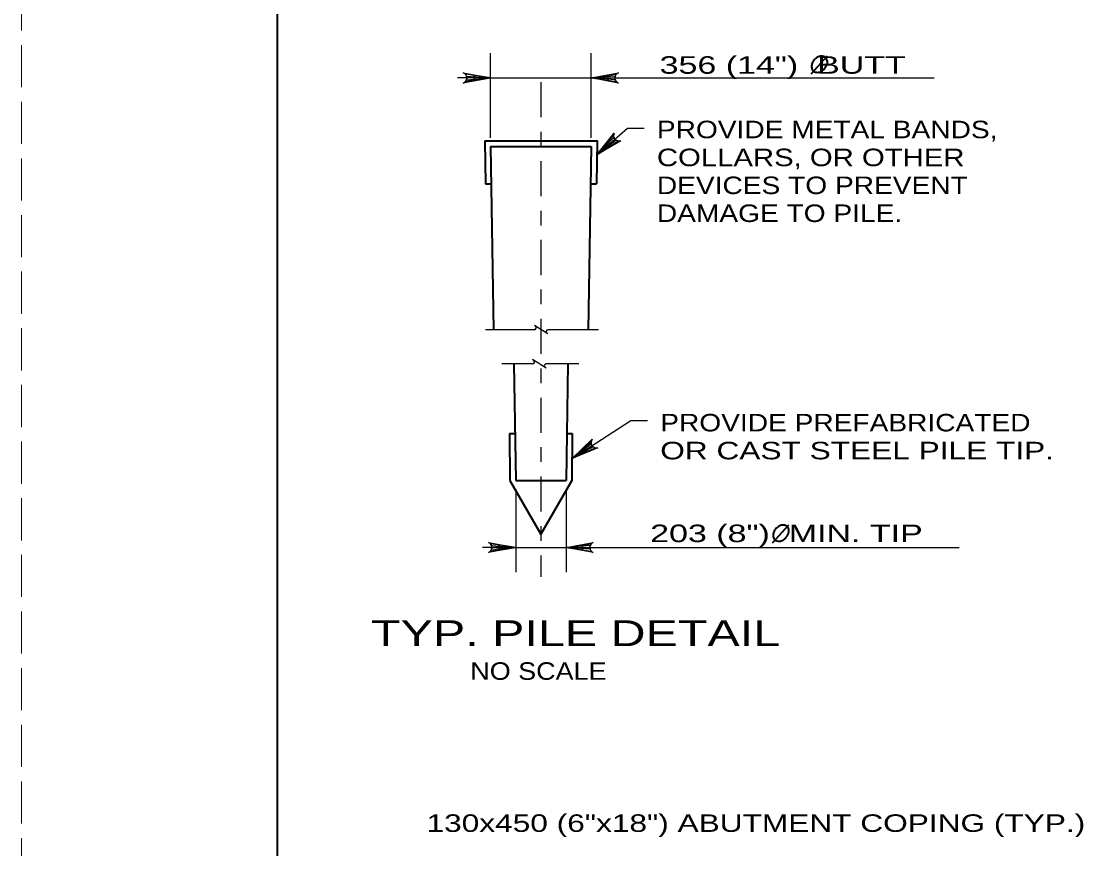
# Model space of a CAD drawing. Extents: x -6.4 to 73.1, y -66 to 0.
# Drawn here: x 0 to 7.37, y -14.43 to -8.76 of the extents above; entities that cross this region are included whole.
import ezdxf
from ezdxf.enums import TextEntityAlignment as Align

# ---------------------------------------------------------------- set-up
doc = ezdxf.new("R2010")
doc.units = 0
doc.header["$LTSCALE"] = 0.048
doc.linetypes.add('DOT_DASHED', pattern=[7.7, 5, -1.2, 0.3, -1.2])
doc.linetypes.add('LONG_DASHED', pattern=[7.5, 6, -1.5])
for name, color, linetype, lineweight in [('1', 7, 'Continuous', 13), ('4', 7, 'Continuous', 25), ('5', 7, 'Continuous', 25), ('63', 7, 'LONG_DASHED', 13)]:
    doc.layers.add(name, color=color, linetype=linetype, lineweight=lineweight)

msp = doc.modelspace()

# ---------------------------------------------------------------- hatches: boundary and pattern name
at = {"layer": '5'}
for points in [[(3.09875, -9.1305), (3.09875, -9.16825), (3.21217, -9.14933)], [(4.01483, -9.1305), (4.01483, -9.16825), (3.90142, -9.14933)], [(4.03808, -9.615), (4.01333, -9.58642), (3.94, -9.67492)], [(3.8765, -11.70867), (3.856, -11.67692), (3.77092, -11.75425)], [(3.27108, -12.34575), (3.27108, -12.3835), (3.38442, -12.36467)], [(3.8425, -12.34575), (3.8425, -12.3835), (3.72908, -12.36467)]]:
    msp.add_hatch(color=256, dxfattribs=at).paths.add_polyline_path(points)

# ---------------------------------------------------------------- linework, layer by layer
at = {"layer": '1', "lineweight": 35}
msp.add_lwpolyline([(1.75, -21.25), (33.25, -21.25), (33.25, -0.75), (1.75, -0.75)], close=True, dxfattribs=at)
at = {"layer": '4', "linetype": 'DOT_DASHED'}
msp.add_line((3.55675, -9.179), (3.55675, -12.56558), dxfattribs=at)
at = {"layer": '4', "lineweight": 35}
for p, q in [((3.17208, -9.5795), (3.17675, -9.87533)), ((3.21217, -9.61892), (3.23192, -10.87383)), ((3.21217, -9.61892), (3.90142, -9.61892)), ((3.90142, -9.61892), (3.88167, -10.87383)), ((3.17675, -9.87533), (3.21617, -9.87533)), ((3.89742, -9.87533), (3.93683, -9.87533)), ((3.37183, -11.10742), (3.38442, -11.90617)), ((3.74175, -11.10742), (3.72908, -11.90617)), ((3.34117, -11.58458), (3.34508, -11.90675)), ((3.34117, -11.58458), (3.38058, -11.58458)), ((3.733, -11.58458), (3.77233, -11.58458)), ((3.77233, -11.58458), (3.7685, -11.90675)), ((3.34508, -11.90675), (3.55675, -12.2735)), ((3.38442, -11.90617), (3.72908, -11.90617)), ((3.7685, -11.90675), (3.55675, -12.2735))]:
    msp.add_line(p, q, dxfattribs=at)
at = {"layer": '4'}
for p, q in [((3.51283, -10.87383), (3.17783, -10.87383)), ((3.60508, -10.90283), (3.51267, -10.84475)), ((3.95233, -10.87383), (3.60608, -10.87383)), ((3.50042, -11.10742), (3.28892, -11.10742)), ((3.59258, -11.1365), (3.50025, -11.07842)), ((3.81633, -11.10742), (3.59367, -11.10742))]:
    msp.add_line(p, q, dxfattribs=at)
at = {"layer": '4', "lineweight": 35}
msp.add_lwpolyline([(3.17208, -9.5795), (3.9415, -9.5795), (3.93683, -9.87533)], dxfattribs=at)
at = {"layer": '4'}
for centre, start, end in [((3.51161, -10.8602), 275.32859, 57.86724), ((3.60612, -10.88742), 90, 240), ((3.49915, -11.09384), 275.32859, 57.86724), ((3.59366, -11.12105), 90, 240)]:
    msp.add_arc(centre, 0.01364, start, end, dxfattribs=at)
at = {"layer": '5'}
for p, q in [((3.21217, -9.55983), (3.21217, -8.97925)), ((3.90142, -9.55983), (3.90142, -8.97925)), ((3.21217, -9.14933), (2.98533, -9.14933)), ((3.21217, -9.14933), (6.251, -9.14933)), ((3.90142, -9.14933), (4.12825, -9.14933)), ((3.38442, -11.96517), (3.38442, -12.53475)), ((3.72908, -11.96517), (3.72908, -12.53475)), ((3.38442, -12.36467), (3.15767, -12.36467)), ((3.38442, -12.36467), (6.42117, -12.36467)), ((3.8425, -12.36467), (3.95592, -12.36467))]:
    msp.add_line(p, q, dxfattribs=at)
at = {"layer": '5', "lineweight": 35}
for p, q in [((5.407, -9.12167), (5.519, -8.999)), ((5.14342, -12.33242), (5.25542, -12.20983))]:
    msp.add_line(p, q, dxfattribs=at)
at = {"layer": '5'}
for points in [[(3.21217, -9.14933), (3.02575, -9.18425), (3.04008, -9.17433), (3.0475, -9.16183), (3.04967, -9.14933), (3.0475, -9.13683), (3.04008, -9.12433), (3.02575, -9.11442), (3.21217, -9.14933), (3.04008, -9.12433), (3.0475, -9.13683), (3.21217, -9.14933), (3.04967, -9.14933), (3.0475, -9.16183), (3.21217, -9.14933), (3.04008, -9.17433)], [(3.90142, -9.14933), (4.08783, -9.11442), (4.0735, -9.12433), (4.06608, -9.13683), (4.06392, -9.14933), (4.06608, -9.16183), (4.0735, -9.17433), (4.08783, -9.18425), (3.90142, -9.14933), (4.0735, -9.17433), (4.06608, -9.16183), (3.90142, -9.14933), (4.06392, -9.14933), (4.06608, -9.13683), (3.90142, -9.14933), (4.0735, -9.12433)], [(3.94, -9.67492), (4.15058, -9.49258), (4.264, -9.49258)], [(3.94, -9.67492), (4.05808, -9.5265), (4.05367, -9.54342), (4.05625, -9.55767), (4.06283, -9.56858), (4.07267, -9.57658), (4.08642, -9.58117), (4.10383, -9.57933), (3.94, -9.67492), (4.08642, -9.58117), (4.07267, -9.57658), (3.94, -9.67492), (4.06283, -9.56858), (4.05625, -9.55767), (3.94, -9.67492), (4.05367, -9.54342)], [(3.77033, -11.75467), (4.17342, -11.49483), (4.28683, -11.49483)], [(3.77033, -11.75467), (3.90808, -11.62425), (3.90142, -11.64042), (3.90192, -11.65492), (3.90692, -11.66658), (3.9155, -11.676), (3.9285, -11.6825), (3.94592, -11.68308), (3.77033, -11.75467), (3.9285, -11.6825), (3.9155, -11.676), (3.77033, -11.75467), (3.90692, -11.66658), (3.90192, -11.65492), (3.77033, -11.75467), (3.90142, -11.64042)], [(3.38442, -12.36467), (3.198, -12.39958), (3.21233, -12.38967), (3.21975, -12.37717), (3.22192, -12.36467), (3.21975, -12.35217), (3.21233, -12.33967), (3.198, -12.32975), (3.38442, -12.36467), (3.21233, -12.33967), (3.21975, -12.35217), (3.38442, -12.36467), (3.22192, -12.36467), (3.21975, -12.37717), (3.38442, -12.36467), (3.21233, -12.38967)], [(3.72908, -12.36467), (3.9155, -12.32975), (3.90117, -12.33967), (3.89375, -12.35217), (3.89158, -12.36467), (3.89375, -12.37717), (3.90117, -12.38967), (3.9155, -12.39958), (3.72908, -12.36467), (3.90117, -12.38967), (3.89375, -12.37717), (3.72908, -12.36467), (3.89158, -12.36467), (3.89375, -12.35217), (3.72908, -12.36467), (3.90117, -12.33967)]]:
    msp.add_lwpolyline(points, dxfattribs=at)
for points in [[(3.09875, -9.1305), (3.09875, -9.16825), (3.21217, -9.14933)], [(4.01483, -9.1305), (4.01483, -9.16825), (3.90142, -9.14933)], [(4.03808, -9.615), (4.01333, -9.58642), (3.94, -9.67492)], [(3.8765, -11.70867), (3.856, -11.67692), (3.77092, -11.75425)], [(3.27108, -12.34575), (3.27108, -12.3835), (3.38442, -12.36467)], [(3.8425, -12.34575), (3.8425, -12.3835), (3.72908, -12.36467)]]:
    msp.add_lwpolyline(points, close=True, dxfattribs=at)
at = {"layer": '5', "lineweight": 35}
for points in [[(5.50742, -9.01117), (5.49867, -9.00425), (5.48992, -9.00192), (5.47892, -9.00092), (5.47267, -9.00092), (5.46192, -9.00342), (5.452, -9.00792), (5.44517, -9.01175), (5.43192, -9.02242), (5.4215, -9.03592), (5.41525, -9.0485), (5.41167, -9.06017), (5.4105, -9.07092), (5.41167, -9.08017), (5.41617, -9.09325), (5.42092, -9.10017), (5.4305, -9.10742), (5.445, -9.11092), (5.4615, -9.11042), (5.48242, -9.10092), (5.49767, -9.08775), (5.50917, -9.07192), (5.51667, -9.05525), (5.51917, -9.03692), (5.51592, -9.025), (5.50792, -9.01117)], [(5.24383, -12.22192), (5.23508, -12.21508), (5.22633, -12.21267), (5.21533, -12.21167), (5.20908, -12.21167), (5.19833, -12.21417), (5.18842, -12.21867), (5.18158, -12.22258), (5.16833, -12.23317), (5.15792, -12.24667), (5.15167, -12.25933), (5.14808, -12.27092), (5.14692, -12.28167), (5.14808, -12.29092), (5.15258, -12.30408), (5.15733, -12.31092), (5.16692, -12.31817), (5.18142, -12.32167), (5.19792, -12.32117), (5.21883, -12.31167), (5.23408, -12.29858), (5.24558, -12.28267), (5.25308, -12.26608), (5.25558, -12.24767), (5.25233, -12.23583), (5.24433, -12.22192)]]:
    msp.add_spline(points, degree=3, dxfattribs=at)
at = {"layer": '63'}
msp.add_lwpolyline([(0, -22), (34, -22), (34, 0), (0, 0)], close=True, dxfattribs=at)

# ---------------------------------------------------------------- texts
at = {"layer": '5'}
for s, height, width, p in [('356 (14")  BUTT', 0.12, 1.45, (5.21317, -9.12058)), ('203 (8")  MIN. TIP', 0.12, 1.45, (5.23879, -12.32825)), ('TYP. PILE DETAIL', 0.1772, 1.4, (3.79454, -13.04067)), ('NO SCALE', 0.12, 1.15, (3.54008, -13.27125))]:
    msp.add_text(s, height=height, dxfattribs=dict(at, width=width)).set_placement(p, align=Align.CENTER)
for s, width, p in [('PROVIDE METAL BANDS,', 1.2, (4.35142, -9.56233)), ('COLLARS, OR OTHER ', 1.25, (4.35142, -9.75358)), ('DEVICES TO PREVENT', 1.2, (4.35142, -9.94475)), ('DAMAGE TO PILE.', 1.2, (4.35142, -10.136)), ('PROVIDE PREFABRICATED', 1.2, (4.3745, -11.57008)), ('OR CAST STEEL PILE TIP.', 1.35, (4.3745, -11.76133))]:
    msp.add_text(s, height=0.12, dxfattribs=dict(at, width=width)).set_placement(p)
at = {"layer": '5', "width": 1.35}
msp.add_text('130x450 (6"x18") ABUTMENT COPING (TYP.)', height=0.12, dxfattribs=at).set_placement((7.28525, -14.31267), align=Align.RIGHT)

doc.saveas('drawing.dxf')
